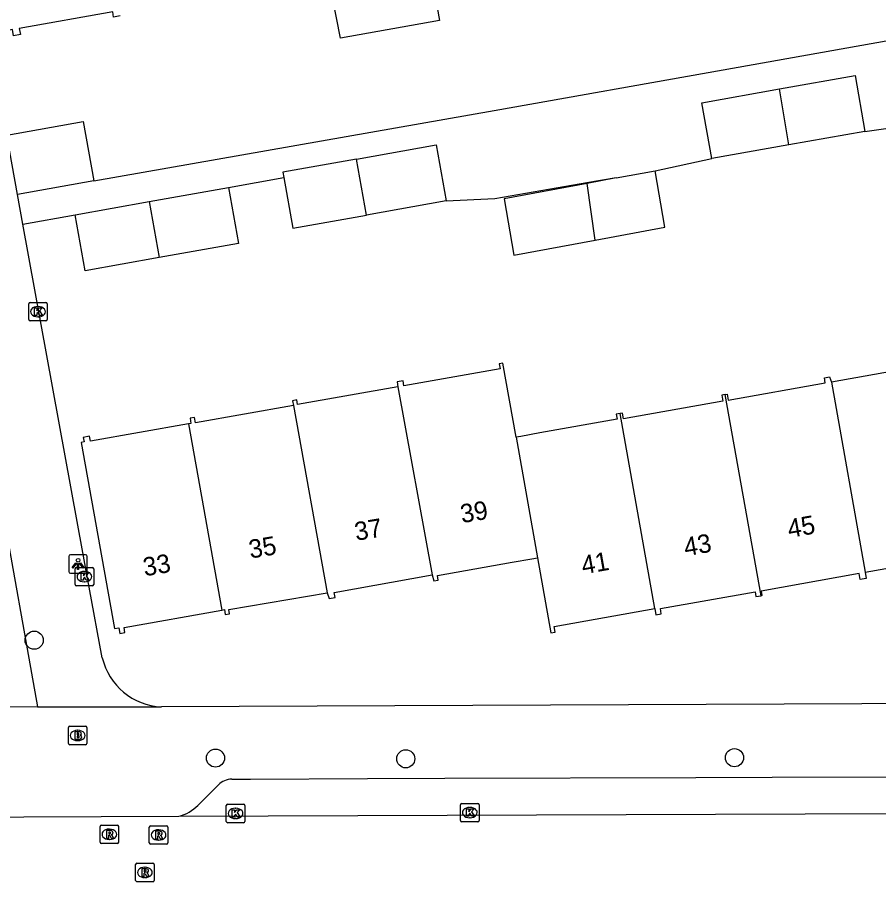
# Model space of a CAD drawing. Extents: x 157793 to 159380, y 380882 to 382313.
# Drawn here: x 158385.51 to 158432.1, y 381262.05 to 381308.82 of the extents above; entities that cross this region are included whole.
import ezdxf

# ---------------------------------------------------------------- set-up
doc = ezdxf.new("R2010")
doc.units = 0
for name, color, linetype in [('IMGEO_Boom', 7, 'Continuous'), ('IMGEO_Brandkraan', 7, 'Continuous'), ('IMGEO_Kolk', 7, 'Continuous'), ('IMGEO_Lichtpunt', 7, 'Continuous'), ('IMGEO_Pand', 7, 'Continuous'), ('IMGEO_Pand_nummerreeks', 7, 'Continuous'), ('IMGEO_Rijbaan_lokaal_gesloten', 7, 'Continuous'), ('IMGEO_Rioolput', 7, 'Continuous'), ('IMGEO_Voetpad_open', 7, 'Continuous')]:
    doc.layers.add(name, color=color, linetype=linetype)

msp = doc.modelspace()

# ---------------------------------------------------------------- linework, layer by layer
at = {"layer": 'IMGEO_Boom'}
for centre in [(158386.423, 381275.115), (158396.229, 381268.737), (158406.521, 381268.696), (158424.297, 381268.757)]:
    msp.add_circle(centre, 0.489, dxfattribs=at)
at = {"layer": 'IMGEO_Brandkraan'}
for p, q in [((158388.277, 381269.532), (158388.277, 381270.384)), ((158388.352, 381270.458), (158389.204, 381270.458)), ((158389.278, 381270.384), (158389.278, 381269.532)), ((158388.765, 381270.238), (158388.79, 381270.238)), ((158389.204, 381269.458), (158388.352, 381269.458)), ((158388.788, 381269.678), (158388.763, 381269.678))]:
    msp.add_line(p, q, dxfattribs=at)
for points in [[(158388.277, 381269.532), (158388.277, 381270.384)], [(158388.352, 381270.458), (158389.204, 381270.458)], [(158389.278, 381270.384), (158389.278, 381269.532)], [(158388.625, 381270.158), (158388.625, 381269.758), (158388.838, 381269.758)], [(158388.856, 381270.158), (158388.625, 381270.158)], [(158388.804, 381270.077), (158388.75, 381270.077), (158388.75, 381270.001)], [(158388.75, 381270.001), (158388.803, 381270.001)], [(158388.812, 381269.925), (158388.75, 381269.925), (158388.75, 381269.844)], [(158388.75, 381269.844), (158388.812, 381269.844)], [(158389.204, 381269.458), (158388.352, 381269.458)]]:
    msp.add_lwpolyline(points, dxfattribs=at)
for centre, radius, start, end in [((158388.354, 381270.382), 0.0765, 91.552, 178.448), ((158388.354, 381270.382), 0.0765, 91.552, 178.448), ((158389.202, 381270.382), 0.0765, 1.552, 88.448), ((158389.202, 381270.382), 0.0765, 1.552, 88.448), ((158388.805, 381270.039), 0.0379, 267.8285, 90.9355), ((158388.813, 381269.884), 0.0404, 269.8759, 90.5077), ((158388.86, 381270.013), 0.145, 59.4692, 91.5367), ((158388.885, 381270.06), 0.0922, 285.5137, 58.1501), ((158388.89, 381269.868), 0.105, 301.3115, 78.989), ((158388.354, 381269.534), 0.0765, 181.552, 268.448), ((158388.354, 381269.534), 0.0765, 181.552, 268.448), ((158388.844, 381270.009), 0.251, 268.6676, 293.5347), ((158389.202, 381269.534), 0.0765, 271.552, 358.448), ((158389.202, 381269.534), 0.0765, 271.552, 358.448)]:
    msp.add_arc(centre, radius, start, end, dxfattribs=at)
for centre, major_axis, ratio, start_param, end_param in [((158388.764, 381269.958), (-0.387, 0.002), 0.722429, 4.712389, 7.853982), ((158388.789, 381269.958), (-0.39, 0.002), 0.717154, 1.570796, 4.712389)]:
    msp.add_ellipse(centre, major_axis=major_axis, ratio=ratio, start_param=start_param, end_param=end_param, dxfattribs=at)
at = {"layer": 'IMGEO_Kolk'}
for p, q in [((158386.126, 381292.464), (158386.126, 381293.316)), ((158386.201, 381293.39), (158387.053, 381293.39)), ((158387.127, 381293.316), (158387.127, 381292.464)), ((158386.614, 381293.17), (158386.639, 381293.17)), ((158387.053, 381292.39), (158386.201, 381292.39)), ((158386.637, 381292.61), (158386.612, 381292.61)), ((158388.641, 381278.13), (158388.641, 381278.982)), ((158388.716, 381279.056), (158389.568, 381279.056)), ((158389.129, 381278.836), (158389.154, 381278.836)), ((158389.642, 381278.982), (158389.642, 381278.13)), ((158389.152, 381278.276), (158389.127, 381278.276)), ((158389.568, 381278.056), (158388.716, 381278.056)), ((158396.813, 381265.313), (158396.813, 381266.165)), ((158396.888, 381266.239), (158397.74, 381266.239)), ((158397.814, 381266.165), (158397.814, 381265.313)), ((158409.483, 381265.36), (158409.483, 381266.212)), ((158409.558, 381266.286), (158410.41, 381266.286)), ((158410.484, 381266.212), (158410.484, 381265.36)), ((158397.301, 381266.019), (158397.326, 381266.019)), ((158409.971, 381266.066), (158409.996, 381266.066)), ((158397.74, 381265.239), (158396.888, 381265.239)), ((158397.324, 381265.459), (158397.299, 381265.459)), ((158410.41, 381265.286), (158409.558, 381265.286)), ((158409.994, 381265.506), (158409.969, 381265.506))]:
    msp.add_line(p, q, dxfattribs=at)
for points in [[(158386.126, 381292.464), (158386.126, 381293.316)], [(158386.201, 381293.39), (158387.053, 381293.39)], [(158387.127, 381293.316), (158387.127, 381292.464)], [(158386.447, 381293.09), (158386.57, 381293.09), (158386.57, 381292.939), (158386.7, 381293.09), (158386.864, 381293.09), (158386.718, 381292.939), (158386.871, 381292.69), (158386.719, 381292.69), (158386.634, 381292.854), (158386.57, 381292.787), (158386.57, 381292.69), (158386.447, 381292.69), (158386.447, 381293.09)], [(158387.053, 381292.39), (158386.201, 381292.39)], [(158388.641, 381278.13), (158388.641, 381278.982)], [(158388.716, 381279.056), (158389.568, 381279.056)], [(158388.962, 381278.756), (158389.085, 381278.756), (158389.085, 381278.605), (158389.215, 381278.756), (158389.379, 381278.756), (158389.233, 381278.605), (158389.386, 381278.356), (158389.234, 381278.356), (158389.149, 381278.52), (158389.085, 381278.453), (158389.085, 381278.356), (158388.962, 381278.356), (158388.962, 381278.756)], [(158389.642, 381278.982), (158389.642, 381278.13)], [(158389.568, 381278.056), (158388.716, 381278.056)], [(158396.813, 381265.313), (158396.813, 381266.165)], [(158396.888, 381266.239), (158397.74, 381266.239)], [(158397.814, 381266.165), (158397.814, 381265.313)], [(158409.483, 381265.36), (158409.483, 381266.212)], [(158409.558, 381266.286), (158410.41, 381266.286)], [(158410.484, 381266.212), (158410.484, 381265.36)], [(158397.134, 381265.939), (158397.257, 381265.939), (158397.257, 381265.788), (158397.387, 381265.939), (158397.551, 381265.939), (158397.405, 381265.788), (158397.558, 381265.539), (158397.406, 381265.539), (158397.321, 381265.703), (158397.257, 381265.636), (158397.257, 381265.539), (158397.134, 381265.539), (158397.134, 381265.939)], [(158409.804, 381265.986), (158409.927, 381265.986), (158409.927, 381265.835), (158410.057, 381265.986), (158410.221, 381265.986), (158410.075, 381265.835), (158410.228, 381265.586), (158410.076, 381265.586), (158409.991, 381265.75), (158409.927, 381265.683), (158409.927, 381265.586), (158409.804, 381265.586), (158409.804, 381265.986)], [(158397.74, 381265.239), (158396.888, 381265.239)], [(158410.41, 381265.286), (158409.558, 381265.286)]]:
    msp.add_lwpolyline(points, dxfattribs=at)
for centre, start, end in [((158386.203, 381293.314), 91.552, 178.448), ((158386.203, 381293.314), 91.552, 178.448), ((158387.051, 381293.314), 1.552, 88.448), ((158387.051, 381293.314), 1.552, 88.448), ((158386.203, 381292.466), 181.552, 268.448), ((158386.203, 381292.466), 181.552, 268.448), ((158387.051, 381292.466), 271.552, 358.448), ((158387.051, 381292.466), 271.552, 358.448), ((158388.718, 381278.98), 91.552, 178.448), ((158388.718, 381278.98), 91.552, 178.448), ((158389.566, 381278.98), 1.552, 88.448), ((158389.566, 381278.98), 1.552, 88.448), ((158388.718, 381278.132), 181.552, 268.448), ((158388.718, 381278.132), 181.552, 268.448), ((158389.566, 381278.132), 271.552, 358.448), ((158389.566, 381278.132), 271.552, 358.448), ((158396.89, 381266.163), 91.552, 178.448), ((158396.89, 381266.163), 91.552, 178.448), ((158397.738, 381266.163), 1.552, 88.448), ((158397.738, 381266.163), 1.552, 88.448), ((158409.56, 381266.21), 91.552, 178.448), ((158409.56, 381266.21), 91.552, 178.448), ((158410.408, 381266.21), 1.552, 88.448), ((158410.408, 381266.21), 1.552, 88.448), ((158396.89, 381265.315), 181.552, 268.448), ((158396.89, 381265.315), 181.552, 268.448), ((158397.738, 381265.315), 271.552, 358.448), ((158397.738, 381265.315), 271.552, 358.448), ((158409.56, 381265.362), 181.552, 268.448), ((158409.56, 381265.362), 181.552, 268.448), ((158410.408, 381265.362), 271.552, 358.448), ((158410.408, 381265.362), 271.552, 358.448)]:
    msp.add_arc(centre, 0.0765, start, end, dxfattribs=at)
for centre, major_axis, ratio, start_param, end_param in [((158386.613, 381292.89), (-0.387, 0.002), 0.722429, 4.712389, 7.853982), ((158386.638, 381292.89), (-0.39, 0.002), 0.717154, 1.570796, 4.712389), ((158389.128, 381278.556), (-0.387, 0.002), 0.722429, 4.712389, 7.853982), ((158389.153, 381278.556), (-0.39, 0.002), 0.717154, 1.570796, 4.712389), ((158397.3, 381265.739), (-0.387, 0.002), 0.722429, 4.712389, 7.853982), ((158397.325, 381265.739), (-0.39, 0.002), 0.717154, 1.570796, 4.712389), ((158409.97, 381265.786), (-0.387, 0.002), 0.722429, 4.712389, 7.853982), ((158409.995, 381265.786), (-0.39, 0.002), 0.717154, 1.570796, 4.712389)]:
    msp.add_ellipse(centre, major_axis=major_axis, ratio=ratio, start_param=start_param, end_param=end_param, dxfattribs=at)
at = {"layer": 'IMGEO_Lichtpunt'}
for p, q in [((158389.198, 381279.735), (158388.39, 381279.735)), ((158389.198, 381279.735), (158388.39, 381279.735)), ((158388.296, 381279.64), (158388.296, 381278.833)), ((158388.296, 381279.64), (158388.296, 381278.833)), ((158389.292, 381278.833), (158389.292, 381279.64)), ((158389.292, 381278.833), (158389.292, 381279.64)), ((158388.39, 381278.739), (158389.198, 381278.739)), ((158388.39, 381278.739), (158389.198, 381278.739))]:
    msp.add_line(p, q, dxfattribs=at)
for points in [[(158388.67, 381279.304), (158388.709, 381279.276), (158388.521, 381279.014), (158388.483, 381279.041), (158388.67, 381279.304)], [(158388.772, 381279.256), (158388.819, 381279.256), (158388.819, 381278.934), (158388.772, 381278.934), (158388.772, 381279.256)], [(158388.882, 381279.276), (158388.92, 381279.303), (158389.107, 381279.041), (158389.068, 381279.013), (158388.882, 381279.276)]]:
    msp.add_lwpolyline(points, dxfattribs=at)
msp.add_circle((158388.795, 381279.438), 0.0994, dxfattribs=at)
for centre, start, end in [((158388.39, 381279.64), 90, 180), ((158388.39, 381279.64), 90, 180), ((158389.198, 381279.64), 0, 90), ((158389.198, 381279.64), 0, 90), ((158388.39, 381278.833), 180, 270), ((158388.39, 381278.833), 180, 270), ((158389.198, 381278.833), 270, 0), ((158389.198, 381278.833), 270, 360)]:
    msp.add_arc(centre, 0.0946, start, end, dxfattribs=at)
at = {"layer": 'IMGEO_Pand'}
for points in [[(158391.082, 381308.895), (158390.721, 381308.831), (158390.67, 381309.113), (158385.619, 381308.212), (158385.677, 381307.884), (158385.311, 381307.819), (158385.25, 381308.161), (158385.078, 381308.13), (158383.307, 381318.526), (158383.672, 381318.591), (158383.732, 381318.252), (158388.852, 381319.164), (158388.791, 381319.506), (158388.982, 381319.54)], [(158408.003, 381311.814), (158407.784, 381311.775), (158408.342, 381308.641), (158402.981, 381307.685), (158402.368, 381310.819)], [(158426.74, 381304.947), (158430.815, 381305.674), (158431.355, 381302.646)], [(158423.066, 381301.169), (158422.526, 381304.197), (158426.74, 381304.947)], [(158427.244, 381301.913), (158426.74, 381304.947)], [(158384.944, 381302.443), (158389.077, 381303.179), (158389.649, 381299.965)], [(158431.355, 381302.646), (158427.244, 381301.913)], [(158385.516, 381299.229), (158384.944, 381302.443)], [(158403.848, 381301.142), (158408.159, 381301.91), (158408.699, 381298.882)], [(158427.244, 381301.913), (158423.066, 381301.169)], [(158403.848, 381301.142), (158399.87, 381300.433), (158399.921, 381300.145)], [(158404.4, 381298.116), (158403.848, 381301.142)], [(158416.77, 381296.766), (158420.532, 381297.464), (158420.007, 381300.514)], [(158417.904, 381300.124), (158420.007, 381300.514)], [(158389.649, 381299.965), (158385.516, 381299.229)], [(158399.921, 381300.145), (158400.41, 381297.405), (158404.4, 381298.116)], [(158416.323, 381299.83), (158411.838, 381298.999), (158412.364, 381295.949), (158416.77, 381296.766)], [(158417.904, 381300.124), (158416.323, 381299.83)], [(158416.77, 381296.766), (158416.323, 381299.83)], [(158392.635, 381298.846), (158396.933, 381299.612)], [(158396.933, 381299.612), (158397.473, 381296.584), (158393.175, 381295.818)], [(158388.644, 381298.135), (158392.635, 381298.846)], [(158392.635, 381298.846), (158393.175, 381295.818)], [(158408.699, 381298.882), (158404.4, 381298.116)], [(158393.175, 381295.818), (158389.184, 381295.107), (158388.644, 381298.135)], [(158412.486, 381286.097), (158411.773, 381290.097), (158411.576, 381290.062), (158411.622, 381289.805), (158406.422, 381288.879), (158406.375, 381289.143), (158406.05, 381289.085), (158406.095, 381288.832)], [(158435.954, 381286.49), (158435.311, 381290.099), (158435.03, 381290.049), (158434.987, 381290.287), (158434.655, 381290.228), (158434.698, 381289.99), (158429.536, 381289.071)], [(158423.795, 381288.406), (158423.898, 381288.425), (158423.955, 381288.105), (158429.206, 381289.041), (158429.159, 381289.31), (158429.44, 381289.361), (158429.536, 381289.071)], [(158429.536, 381289.071), (158431.357, 381278.8)], [(158406.095, 381288.832), (158400.668, 381287.865), (158400.624, 381288.111), (158400.398, 381288.07), (158400.442, 381287.822)], [(158406.095, 381288.832), (158407.955, 381278.642)], [(158423.795, 381288.406), (158423.614, 381288.374), (158423.672, 381288.046), (158418.297, 381287.088), (158418.241, 381287.402), (158418.118, 381287.38)], [(158425.734, 381277.523), (158423.795, 381288.406)], [(158400.442, 381287.822), (158395.143, 381286.878), (158395.091, 381287.166), (158394.854, 381287.123), (158394.903, 381286.848), (158394.777, 381286.826)], [(158400.442, 381287.822), (158402.267, 381277.676)], [(158418.118, 381287.38), (158417.904, 381287.342), (158417.952, 381287.072), (158413.771, 381286.326), (158412.736, 381286.142), (158412.486, 381286.097)], [(158419.982, 381276.833), (158418.118, 381287.38)], [(158394.777, 381286.826), (158389.467, 381285.88), (158389.419, 381286.15), (158389.075, 381286.089), (158389.119, 381285.841), (158388.973, 381285.815), (158390.768, 381275.741), (158391.001, 381275.779), (158391.054, 381275.478), (158391.333, 381275.527), (158391.284, 381275.805), (158396.573, 381276.748)], [(158394.777, 381286.826), (158396.573, 381276.748)], [(158412.486, 381286.097), (158413.648, 381279.575)], [(158431.357, 381278.8), (158435.523, 381279.543), (158436.637, 381279.741), (158437.08, 381279.82)], [(158407.955, 381278.642), (158408.044, 381278.322), (158408.278, 381278.363), (158408.234, 381278.611), (158412.277, 381279.331), (158413.343, 381279.521), (158413.648, 381279.575)], [(158413.648, 381279.575), (158414.373, 381275.507), (158414.599, 381275.547), (158414.542, 381275.863), (158419.982, 381276.833)], [(158431.357, 381278.8), (158431.417, 381278.459), (158431.099, 381278.402), (158431.042, 381278.721), (158425.733, 381277.775), (158425.777, 381277.531), (158425.734, 381277.523)], [(158402.267, 381277.676), (158402.368, 381277.367), (158402.697, 381277.425), (158402.649, 381277.696), (158407.955, 381278.642)], [(158396.573, 381276.748), (158396.715, 381276.773), (158396.759, 381276.503), (158396.995, 381276.541), (158396.955, 381276.782), (158402.267, 381277.676)], [(158419.982, 381276.833), (158420.043, 381276.49), (158420.337, 381276.543), (158420.287, 381276.823), (158425.409, 381277.736), (158425.455, 381277.473), (158425.734, 381277.523)]]:
    msp.add_lwpolyline(points, dxfattribs=at)
at = {"layer": 'IMGEO_Rijbaan_lokaal_gesloten'}
for points in [[(158394.254, 381265.587), (158447.459, 381265.784)], [(158381.644, 381265.541), (158394.254, 381265.587)]]:
    msp.add_lwpolyline(points, dxfattribs=at)
at = {"layer": 'IMGEO_Rioolput'}
for p, q in [((158389.991, 381264.185), (158389.991, 381265.037)), ((158390.066, 381265.111), (158390.918, 381265.111)), ((158390.479, 381264.891), (158390.504, 381264.891)), ((158390.992, 381265.037), (158390.992, 381264.185)), ((158392.65, 381264.149), (158392.65, 381265.001)), ((158392.725, 381265.075), (158393.577, 381265.075)), ((158393.138, 381264.855), (158393.163, 381264.855)), ((158393.651, 381265.001), (158393.651, 381264.149)), ((158390.502, 381264.331), (158390.477, 381264.331)), ((158393.161, 381264.295), (158393.136, 381264.295)), ((158390.918, 381264.111), (158390.066, 381264.111)), ((158393.577, 381264.075), (158392.725, 381264.075)), ((158391.908, 381262.121), (158391.908, 381262.973)), ((158391.983, 381263.047), (158392.835, 381263.047)), ((158392.396, 381262.827), (158392.421, 381262.827)), ((158392.909, 381262.973), (158392.909, 381262.121)), ((158392.835, 381262.047), (158391.983, 381262.047)), ((158392.419, 381262.267), (158392.394, 381262.267))]:
    msp.add_line(p, q, dxfattribs=at)
for points in [[(158389.991, 381264.185), (158389.991, 381265.037)], [(158390.066, 381265.111), (158390.918, 381265.111)], [(158390.58, 381264.809), (158390.328, 381264.811), (158390.328, 381264.411)], [(158390.506, 381264.73), (158390.452, 381264.73), (158390.452, 381264.649)], [(158390.992, 381265.037), (158390.992, 381264.185)], [(158392.65, 381264.149), (158392.65, 381265.001)], [(158392.725, 381265.075), (158393.577, 381265.075)], [(158393.239, 381264.773), (158392.987, 381264.775), (158392.987, 381264.375)], [(158393.165, 381264.694), (158393.111, 381264.694), (158393.111, 381264.613)], [(158393.651, 381265.001), (158393.651, 381264.149)], [(158390.328, 381264.411), (158390.452, 381264.411), (158390.452, 381264.573), (158390.463, 381264.573)], [(158390.452, 381264.649), (158390.504, 381264.649)], [(158390.51, 381264.544), (158390.581, 381264.411), (158390.721, 381264.411), (158390.656, 381264.537)], [(158392.987, 381264.375), (158393.111, 381264.375), (158393.111, 381264.537), (158393.122, 381264.537)], [(158393.111, 381264.613), (158393.163, 381264.613)], [(158393.169, 381264.508), (158393.24, 381264.375), (158393.38, 381264.375), (158393.315, 381264.501)], [(158390.918, 381264.111), (158390.066, 381264.111)], [(158393.577, 381264.075), (158392.725, 381264.075)], [(158391.908, 381262.121), (158391.908, 381262.973)], [(158391.983, 381263.047), (158392.835, 381263.047)], [(158392.909, 381262.973), (158392.909, 381262.121)], [(158392.497, 381262.745), (158392.245, 381262.747), (158392.245, 381262.347)], [(158392.245, 381262.347), (158392.369, 381262.347), (158392.369, 381262.509), (158392.38, 381262.509)], [(158392.423, 381262.666), (158392.369, 381262.666), (158392.369, 381262.585)], [(158392.369, 381262.585), (158392.421, 381262.585)], [(158392.427, 381262.48), (158392.498, 381262.347), (158392.638, 381262.347), (158392.573, 381262.473)], [(158392.835, 381262.047), (158391.983, 381262.047)]]:
    msp.add_lwpolyline(points, dxfattribs=at)
for centre, radius, start, end in [((158390.068, 381265.035), 0.0765, 91.552, 178.448), ((158390.068, 381265.035), 0.0765, 91.552, 178.448), ((158390.512, 381264.634), 0.0964, 77.0061, 93.1865), ((158390.526, 381264.691), 0.0378, 276.6634, 79.6772), ((158390.579, 381264.699), 0.109, 350.3612, 89.416), ((158390.916, 381265.035), 0.0765, 1.552, 88.448), ((158390.916, 381265.035), 0.0765, 1.552, 88.448), ((158392.727, 381264.999), 0.0765, 91.552, 178.448), ((158392.727, 381264.999), 0.0765, 91.552, 178.448), ((158393.171, 381264.598), 0.0964, 77.0061, 93.1865), ((158393.185, 381264.655), 0.0378, 276.6634, 79.6772), ((158393.238, 381264.663), 0.109, 350.3612, 89.416), ((158393.575, 381264.999), 0.0765, 1.552, 88.448), ((158393.575, 381264.999), 0.0765, 1.552, 88.448), ((158390.462, 381264.52), 0.0533, 26.0293, 88.6989), ((158390.488, 381264.838), 0.19, 274.7715, 282.9687), ((158390.577, 381264.699), 0.112, 277.5842, 350.9817), ((158390.561, 381264.484), 0.108, 29.5134, 73.7905), ((158393.121, 381264.484), 0.0533, 26.0293, 88.6989), ((158393.147, 381264.802), 0.19, 274.7715, 282.9687), ((158393.236, 381264.663), 0.112, 277.5842, 350.9817), ((158393.22, 381264.448), 0.108, 29.5134, 73.7905), ((158390.068, 381264.187), 0.0765, 181.552, 268.448), ((158390.068, 381264.187), 0.0765, 181.552, 268.448), ((158390.916, 381264.187), 0.0765, 271.552, 358.448), ((158390.916, 381264.187), 0.0765, 271.552, 358.448), ((158392.727, 381264.151), 0.0765, 181.552, 268.448), ((158392.727, 381264.151), 0.0765, 181.552, 268.448), ((158393.575, 381264.151), 0.0765, 271.552, 358.448), ((158393.575, 381264.151), 0.0765, 271.552, 358.448), ((158391.985, 381262.971), 0.0765, 91.552, 178.448), ((158391.985, 381262.971), 0.0765, 91.552, 178.448), ((158392.833, 381262.971), 0.0765, 1.552, 88.448), ((158392.833, 381262.971), 0.0765, 1.552, 88.448), ((158392.379, 381262.456), 0.0533, 26.0293, 88.6989), ((158392.405, 381262.774), 0.19, 274.7715, 282.9687), ((158392.429, 381262.57), 0.0964, 77.0061, 93.1865), ((158392.443, 381262.627), 0.0378, 276.6634, 79.6772), ((158392.496, 381262.635), 0.109, 350.3612, 89.416), ((158392.494, 381262.635), 0.112, 277.5842, 350.9817), ((158392.478, 381262.42), 0.108, 29.5134, 73.7905), ((158391.985, 381262.123), 0.0765, 181.552, 268.448), ((158391.985, 381262.123), 0.0765, 181.552, 268.448), ((158392.833, 381262.123), 0.0765, 271.552, 358.448), ((158392.833, 381262.123), 0.0765, 271.552, 358.448)]:
    msp.add_arc(centre, radius, start, end, dxfattribs=at)
for centre, major_axis, ratio, start_param, end_param in [((158390.478, 381264.611), (-0.387, 0.002), 0.722429, 4.712389, 7.853982), ((158390.503, 381264.611), (-0.39, 0.002), 0.717154, 1.570796, 4.712389), ((158393.137, 381264.575), (-0.387, 0.002), 0.722429, 4.712389, 7.853982), ((158393.162, 381264.575), (-0.39, 0.002), 0.717154, 1.570796, 4.712389), ((158392.395, 381262.547), (-0.387, 0.002), 0.722429, 4.712389, 7.853982), ((158392.42, 381262.547), (-0.39, 0.002), 0.717154, 1.570796, 4.712389)]:
    msp.add_ellipse(centre, major_axis=major_axis, ratio=ratio, start_param=start_param, end_param=end_param, dxfattribs=at)
at = {"layer": 'IMGEO_Voetpad_open'}
for points in [[(158389.649, 381299.965), (158411.301, 381303.769), (158423.681, 381305.976), (158439.193, 381308.742)], [(158431.355, 381302.646), (158434.518, 381303.097)], [(158381.729, 381301.305), (158384.981, 381283.287), (158384.495, 381283.285), (158384.556, 381282.944), (158386.607, 381271.512)], [(158420.007, 381300.514), (158423.066, 381301.169)], [(158396.933, 381299.612), (158399.921, 381300.145)], [(158408.699, 381298.882), (158411.33, 381299.017), (158416.316, 381299.877), (158417.9, 381300.15), (158417.904, 381300.124)], [(158385.808, 381297.63), (158385.516, 381299.229)], [(158385.808, 381297.63), (158388.644, 381298.135)], [(158390.104, 381274.163), (158389.398, 381277.977), (158385.808, 381297.63)], [(158448.288, 381271.738), (158448.019, 381271.737), (158393.303, 381271.505)], [(158386.607, 381271.512), (158359.289, 381271.383)], [(158386.607, 381271.512), (158393.303, 381271.505)], [(158397.113, 381267.591), (158398.123, 381267.602), (158404.457, 381267.623), (158408.624, 381267.65), (158422.206, 381267.693), (158426.333, 381267.709), (158432.987, 381267.722), (158436.58, 381267.729), (158442.946, 381267.765), (158444.184, 381267.778)], [(158395.278, 381266.179), (158396.387, 381267.283)]]:
    msp.add_lwpolyline(points, dxfattribs=at)
for centre, radius, start, end in [((158393.472, 381274.963), 3.462, 193.3598, 267.1949), ((158397.102, 381266.607), 0.984, 89.3651, 136.6124), ((158393.656, 381267.802), 2.295, 285.0973, 314.9693)]:
    msp.add_arc(centre, radius, start, end, dxfattribs=at)

# ---------------------------------------------------------------- texts
at = {"layer": 'IMGEO_Pand_nummerreeks'}
for s, rotation, p in [('39', 9.5111, (158409.557, 381281.445)), ('37', 9.5135, (158403.837, 381280.487)), ('45', 10.0325, (158427.258, 381280.642)), ('35', 9.5135, (158398.117, 381279.528)), ('43', 10.032, (158421.651, 381279.65)), ('33', 9.5135, (158392.397, 381278.569)), ('41', 10.0325, (158416.11, 381278.67))]:
    msp.add_text(s, height=1, rotation=rotation, dxfattribs=at).set_placement(p)

doc.saveas('drawing.dxf')
